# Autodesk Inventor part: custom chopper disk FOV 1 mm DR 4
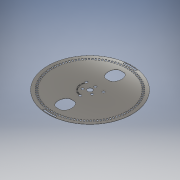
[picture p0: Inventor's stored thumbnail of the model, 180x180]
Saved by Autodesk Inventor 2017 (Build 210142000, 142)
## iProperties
Created: 2016-09
Part Number: custom chopper disk FOV 1 mm DR 4
Material: Generic
Document SubType Name: Modeling
Designer: Radek
Density: 1 g/cm^3
Appearance: Mirror
Author: Radek
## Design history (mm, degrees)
workplane "Work Plane1"
sketch "Sketch1"
  geometry: L1 (-46.781, 4.422)-(-44.253, 4.183) reference; L2 (-44.362, 2.791)-(-46.897, 2.951) reference; L3 (-46.411, 7.351)-(-43.903, 6.954) reference; L4 (-44.099, 5.571)-(-46.619, 5.889) reference; L5 (-45.858, 10.251)-(-43.38, 9.696) reference; L6 (-43.663, 8.329)-(-46.158, 8.805) reference; L7 (-45.124, 13.11)-(-42.685, 12.401) reference; L8 (-43.054, 11.054)-(-45.514, 11.686) reference; L9 (-44.212, 15.917)-(-41.822, 15.057) reference; L10 (-42.274, 13.736)-(-44.69, 14.521) reference; L11 (-43.125, 18.662)-(-40.794, 17.653) reference; L12 (-41.329, 16.363)-(-43.69, 17.298) reference; L13 (-41.868, 21.333)-(-39.605, 20.18) reference; L14 (-40.22, 18.926)-(-42.518, 20.007) reference; L15 (-40.446, 23.92)-(-38.26, 22.627) reference; L16 (-38.952, 21.414)-(-41.178, 22.638) reference; L17 (-38.865, 26.412)-(-36.764, 24.985) reference; L18 (-37.53, 23.818)-(-39.675, 25.179) reference; L19 (-37.129, 28.801)-(-35.122, 27.244) reference; L20 (-35.961, 26.127)-(-38.016, 27.62) reference; L21 (-35.248, 31.075)-(-33.342, 29.395) reference; L22 (-34.249, 28.333)-(-36.206, 29.953) reference; L23 (-33.227, 33.227)-(-31.431, 31.431) reference; L24 (-32.403, 30.428)-(-34.254, 32.167) reference; L25 (-31.075, 35.248)-(-29.395, 33.342) reference; L26 (-30.428, 32.403)-(-32.167, 34.254) reference; L27 (-28.801, 37.129)-(-27.244, 35.122) reference; L28 (-28.333, 34.249)-(-29.953, 36.206) reference; L29 (-26.412, 38.865)-(-24.985, 36.764) reference; L30 (-26.127, 35.961)-(-27.62, 38.016) reference; L31 (-23.92, 40.446)-(-22.627, 38.26) reference; L32 (-23.818, 37.53)-(-25.179, 39.675) reference; L33 (-21.333, 41.868)-(-20.18, 39.605) reference; L34 (-21.414, 38.952)-(-22.638, 41.178) reference; L35 (-18.662, 43.125)-(-17.653, 40.794) reference; L36 (-18.926, 40.22)-(-20.007, 42.518) reference; L37 (-15.917, 44.212)-(-15.057, 41.822) reference; L38 (-16.363, 41.329)-(-17.298, 43.69) reference; L39 (-13.11, 45.124)-(-12.401, 42.685) reference; L40 (-13.736, 42.274)-(-14.521, 44.69) reference; L41 (-10.251, 45.858)-(-9.696, 43.38) reference; L42 (-11.054, 43.054)-(-11.686, 45.514) reference; L43 (-7.351, 46.411)-(-6.954, 43.903) reference; L44 (-8.329, 43.663)-(-8.805, 46.158) reference; L45 (-4.422, 46.781)-(-4.183, 44.253) reference; L46 (-5.571, 44.099)-(-5.889, 46.619) reference; L47 (-1.476, 46.967)-(-1.396, 44.428) reference; L48 (-2.791, 44.362)-(-2.951, 46.897) reference; L49 (1.476, 46.967)-(1.396, 44.428) reference; L50 (0, 44.45)-(0, 46.99) reference; L51 (4.422, 46.781)-(4.183, 44.253) reference; L52 (2.791, 44.362)-(2.951, 46.897) reference; L53 (7.351, 46.411)-(6.954, 43.903) reference; L54 (5.571, 44.099)-(5.889, 46.619) reference; L55 (10.251, 45.858)-(9.696, 43.38) reference; L56 (8.329, 43.663)-(8.805, 46.158) reference; L57 (13.11, 45.124)-(12.401, 42.685) reference; L58 (11.054, 43.054)-(11.686, 45.514) reference; L59 (15.917, 44.212)-(15.057, 41.822) reference; L60 (13.736, 42.274)-(14.521, 44.69) reference; L61 (18.662, 43.125)-(17.653, 40.794) reference; L62 (16.363, 41.329)-(17.298, 43.69) reference; L63 (21.333, 41.868)-(20.18, 39.605) reference; L64 (18.926, 40.22)-(20.007, 42.518) reference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; C1 r 50.8 at (0, 0) reference; C2 r 2.984 at (0, 0) reference; C3 r 1.524 at (0, 6.553) reference; C4 r 1.524 at (10.339, 5.969) reference; C5 r 2.984 at (0, 0) reference; C6 r 1.524 at (0, -11.938) reference; C7 r 1.524 at (-5.675, -3.277) reference; C8 r 1.524 at (-10.339, 5.969) reference; C9 r 1.524 at (5.675, -3.277) reference; C10 r 50.8 at (0, 0) reference; C11 r 1.524 at (-5.675, -3.277) reference; C12 r 1.524 at (-10.339, 5.969) reference; C13 r 1.524 at (0, 6.553) reference; C14 r 1.524 at (10.339, 5.969) reference; C15 r 1.524 at (5.675, -3.277) reference; C16 r 1.524 at (0, -11.938) reference; C17 r 2.984 at (0, 0) reference; A1 r 17.081 centre (0, 0) between (0, -17.081) and (17.081, 0) reference; A2 r 17.081 centre (0, 0) between (0, 17.081) and (-17.081, 0) reference; A3 r 43.18 centre (0, 0) between (0, 43.18) and (-43.18, 0) reference; A4 r 43.18 centre (0, 0) between (0, -43.18) and (43.18, 0) reference; A5 r 44.45 centre (0, 0) between (-44.253, 4.183) and (-44.362, 2.791) reference; A6 r 46.99 centre (0, 0) between (-46.781, 4.422) and (-46.897, 2.951) reference; A7 r 44.45 centre (0, 0) between (-43.903, 6.954) and (-44.099, 5.571) reference; A8 r 46.99 centre (0, 0) between (-46.411, 7.351) and (-46.619, 5.889) reference; A9 r 44.45 centre (0, 0) between (-43.38, 9.696) and (-43.663, 8.329) reference; A10 r 46.99 centre (0, 0) between (-45.858, 10.251) and (-46.158, 8.805) reference; A11 r 44.45 centre (0, 0) between (-42.685, 12.401) and (-43.054, 11.054) reference; A12 r 46.99 centre (0, 0) between (-45.124, 13.11) and (-45.514, 11.686) reference; A13 r 44.45 centre (0, 0) between (-41.822, 15.057) and (-42.274, 13.736) reference; A14 r 46.99 centre (0, 0) between (-44.212, 15.917) and (-44.69, 14.521) reference; A15 r 44.45 centre (0, 0) between (-40.794, 17.653) and (-41.329, 16.363) reference; A16 r 46.99 centre (0, 0) between (-43.125, 18.662) and (-43.69, 17.298) reference; A17 r 44.45 centre (0, 0) between (-39.605, 20.18) and (-40.22, 18.926) reference; A18 r 46.99 centre (0, 0) between (-41.868, 21.333) and (-42.518, 20.007) reference; A19 r 44.45 centre (0, 0) between (-38.26, 22.627) and (-38.952, 21.414) reference; A20 r 46.99 centre (0, 0) between (-40.446, 23.92) and (-41.178, 22.638) reference; A21 r 44.45 centre (0, 0) between (-36.764, 24.985) and (-37.53, 23.818) reference; A22 r 46.99 centre (0, 0) between (-38.865, 26.412) and (-39.675, 25.179) reference; A23 r 44.45 centre (0, 0) between (-35.122, 27.244) and (-35.961, 26.127) reference; A24 r 46.99 centre (0, 0) between (-37.129, 28.801) and (-38.016, 27.62) reference; A25 r 44.45 centre (0, 0) between (-33.342, 29.395) and (-34.249, 28.333) reference; A26 r 46.99 centre (0, 0) between (-35.248, 31.075) and (-36.206, 29.953) reference; A27 r 44.45 centre (0, 0) between (-31.431, 31.431) and (-32.403, 30.428) reference; A28 r 46.99 centre (0, 0) between (-33.227, 33.227) and (-34.254, 32.167) reference; A29 r 44.45 centre (0, 0) between (-29.395, 33.342) and (-30.428, 32.403) reference; A30 r 46.99 centre (0, 0) between (-31.075, 35.248) and (-32.167, 34.254) reference; A31 r 44.45 centre (0, 0) between (-27.244, 35.122) and (-28.333, 34.249) reference; A32 r 46.99 centre (0, 0) between (-28.801, 37.129) and (-29.953, 36.206) reference; A33 r 44.45 centre (0, 0) between (-24.985, 36.764) and (-26.127, 35.961) reference; A34 r 46.99 centre (0, 0) between (-26.412, 38.865) and (-27.62, 38.016) reference; A35 r 44.45 centre (0, 0) between (-22.627, 38.26) and (-23.818, 37.53) reference; A36 r 46.99 centre (0, 0) between (-23.92, 40.446) and (-25.179, 39.675) reference; A37 r 44.45 centre (0, 0) between (-20.18, 39.605) and (-21.414, 38.952) reference; A38 r 46.99 centre (0, 0) between (-21.333, 41.868) and (-22.638, 41.178) reference; A39 r 44.45 centre (0, 0) between (-17.653, 40.794) and (-18.926, 40.22) reference; A40 r 46.99 centre (0, 0) between (-18.662, 43.125) and (-20.007, 42.518) reference; A41 r 44.45 centre (0, 0) between (-15.057, 41.822) and (-16.363, 41.329) reference; A42 r 46.99 centre (0, 0) between (-15.917, 44.212) and (-17.298, 43.69) reference; A43 r 44.45 centre (0, 0) between (-12.401, 42.685) and (-13.736, 42.274) reference; A44 r 46.99 centre (0, 0) between (-13.11, 45.124) and (-14.521, 44.69) reference; A45 r 44.45 centre (0, 0) between (-9.696, 43.38) and (-11.054, 43.054) reference; A46 r 46.99 centre (0, 0) between (-10.251, 45.858) and (-11.686, 45.514) reference; A47 r 44.45 centre (0, 0) between (-6.954, 43.903) and (-8.329, 43.663) reference; A48 r 46.99 centre (0, 0) between (-7.351, 46.411) and (-8.805, 46.158) reference; A49 r 44.45 centre (0, 0) between (-4.183, 44.253) and (-5.571, 44.099) reference; A50 r 46.99 centre (0, 0) between (-4.422, 46.781) and (-5.889, 46.619) reference; A51 r 44.45 centre (0, 0) between (-1.396, 44.428) and (-2.791, 44.362) reference; A52 r 46.99 centre (0, 0) between (-1.476, 46.967) and (-2.951, 46.897) reference; A53 r 44.45 centre (0, 0) between (1.396, 44.428) and (0, 44.45) reference; A54 r 46.99 centre (0, 0) between (1.476, 46.967) and (0, 46.99) reference; A55 r 44.45 centre (0, 0) between (4.183, 44.253) and (2.791, 44.362) reference; A56 r 46.99 centre (0, 0) between (4.422, 46.781) and (2.951, 46.897) reference; A57 r 44.45 centre (0, 0) between (6.954, 43.903) and (5.571, 44.099) reference; A58 r 46.99 centre (0, 0) between (7.351, 46.411) and (5.889, 46.619) reference; A59 r 44.45 centre (0, 0) between (9.696, 43.38) and (8.329, 43.663) reference; A60 r 46.99 centre (0, 0) between (10.251, 45.858) and (8.805, 46.158) reference; A61 r 44.45 centre (0, 0) between (12.401, 42.685) and (11.054, 43.054) reference; A62 r 46.99 centre (0, 0) between (13.11, 45.124) and (11.686, 45.514) reference; A63 r 44.45 centre (0, 0) between (15.057, 41.822) and (13.736, 42.274) reference; A64 r 46.99 centre (0, 0) between (15.917, 44.212) and (14.521, 44.69) reference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; 1 further point
  constraints: 8 end point, 2 collinear, 1 parallel
extrude "Extrusion2" new body sketch "Sketch1" distance "d2" = 0.254; taper "d3" = 0 deg
sketch "Sketch2"
  geometry: L1 (-46.781, 4.422)-(-44.253, 4.183) reference; L2 (-44.362, 2.791)-(-46.897, 2.951) reference; L3 (-46.411, 7.351)-(-43.903, 6.954) reference; L4 (-44.099, 5.571)-(-46.619, 5.889) reference; L5 (-45.858, 10.251)-(-43.38, 9.696) reference; L6 (-43.663, 8.329)-(-46.158, 8.805) reference; L7 (-45.124, 13.11)-(-42.685, 12.401) reference; L8 (-43.054, 11.054)-(-45.514, 11.686) reference; L9 (-44.212, 15.917)-(-41.822, 15.057) reference; L10 (-42.274, 13.736)-(-44.69, 14.521) reference; L11 (-43.125, 18.662)-(-40.794, 17.653) reference; L12 (-41.329, 16.363)-(-43.69, 17.298) reference; L13 (-41.868, 21.333)-(-39.605, 20.18) reference; L14 (-40.22, 18.926)-(-42.518, 20.007) reference; L15 (-40.446, 23.92)-(-38.26, 22.627) reference; L16 (-38.952, 21.414)-(-41.178, 22.638) reference; L17 (-38.865, 26.412)-(-36.764, 24.985) reference; L18 (-37.53, 23.818)-(-39.675, 25.179) reference; L19 (-37.129, 28.801)-(-35.122, 27.244) reference; L20 (-35.961, 26.127)-(-38.016, 27.62) reference; L21 (-35.248, 31.075)-(-33.342, 29.395) reference; L22 (-34.249, 28.333)-(-36.206, 29.953) reference; L23 (-33.227, 33.227)-(-31.431, 31.431) reference; L24 (-32.403, 30.428)-(-34.254, 32.167) reference; L25 (-31.075, 35.248)-(-29.395, 33.342) reference; L26 (-30.428, 32.403)-(-32.167, 34.254) reference; L27 (-28.801, 37.129)-(-27.244, 35.122) reference; L28 (-28.333, 34.249)-(-29.953, 36.206) reference; L29 (-26.412, 38.865)-(-24.985, 36.764) reference; L30 (-26.127, 35.961)-(-27.62, 38.016) reference; L31 (-23.92, 40.446)-(-22.627, 38.26) reference; L32 (-23.818, 37.53)-(-25.179, 39.675) reference; L33 (-21.333, 41.868)-(-20.18, 39.605) reference; L34 (-21.414, 38.952)-(-22.638, 41.178) reference; L35 (-18.662, 43.125)-(-17.653, 40.794) reference; L36 (-18.926, 40.22)-(-20.007, 42.518) reference; L37 (-15.917, 44.212)-(-15.057, 41.822) reference; L38 (-16.363, 41.329)-(-17.298, 43.69) reference; L39 (-13.11, 45.124)-(-12.401, 42.685) reference; L40 (-13.736, 42.274)-(-14.521, 44.69) reference; L41 (-10.251, 45.858)-(-9.696, 43.38) reference; L42 (-11.054, 43.054)-(-11.686, 45.514) reference; L43 (-7.351, 46.411)-(-6.954, 43.903) reference; L44 (-8.329, 43.663)-(-8.805, 46.158) reference; L45 (-4.422, 46.781)-(-4.183, 44.253) reference; L46 (-5.571, 44.099)-(-5.889, 46.619) reference; L47 (-1.476, 46.967)-(-1.396, 44.428) reference; L48 (-2.791, 44.362)-(-2.951, 46.897) reference; L49 (1.476, 46.967)-(1.396, 44.428) reference; L50 (0, 44.45)-(0, 46.99) reference; L51 (4.422, 46.781)-(4.183, 44.253) reference; L52 (2.791, 44.362)-(2.951, 46.897) reference; L53 (7.351, 46.411)-(6.954, 43.903) reference; L54 (5.571, 44.099)-(5.889, 46.619) reference; L55 (10.251, 45.858)-(9.696, 43.38) reference; L56 (8.329, 43.663)-(8.805, 46.158) reference; L57 (13.11, 45.124)-(12.401, 42.685) reference; L58 (11.054, 43.054)-(11.686, 45.514) reference; L59 (15.917, 44.212)-(15.057, 41.822) reference; L60 (13.736, 42.274)-(14.521, 44.69) reference; L61 (18.662, 43.125)-(17.653, 40.794) reference; L62 (16.363, 41.329)-(17.298, 43.69) reference; L63 (21.333, 41.868)-(20.18, 39.605) reference; L64 (18.926, 40.22)-(20.007, 42.518) reference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; C1 r 50.8 at (0, 0) reference; C2 r 1.524 at (-5.675, -3.277) reference; C3 r 1.524 at (-10.339, 5.969) reference; C4 r 1.524 at (0, 6.553) reference; C5 r 1.524 at (10.339, 5.969) reference; C6 r 1.524 at (5.675, -3.277) reference; C7 r 1.524 at (0, -11.938) reference; C8 r 2.984 at (0, 0) reference; A1 r 44.45 centre (0, 0) between (-44.253, 4.183) and (-44.362, 2.791) reference; A2 r 46.99 centre (0, 0) between (-46.781, 4.422) and (-46.897, 2.951) reference; A3 r 44.45 centre (0, 0) between (-43.903, 6.954) and (-44.099, 5.571) reference; A4 r 46.99 centre (0, 0) between (-46.411, 7.351) and (-46.619, 5.889) reference; A5 r 44.45 centre (0, 0) between (-43.38, 9.696) and (-43.663, 8.329) reference; A6 r 46.99 centre (0, 0) between (-45.858, 10.251) and (-46.158, 8.805) reference; A7 r 44.45 centre (0, 0) between (-42.685, 12.401) and (-43.054, 11.054) reference; A8 r 46.99 centre (0, 0) between (-45.124, 13.11) and (-45.514, 11.686) reference; A9 r 44.45 centre (0, 0) between (-41.822, 15.057) and (-42.274, 13.736) reference; A10 r 46.99 centre (0, 0) between (-44.212, 15.917) and (-44.69, 14.521) reference; A11 r 44.45 centre (0, 0) between (-40.794, 17.653) and (-41.329, 16.363) reference; A12 r 46.99 centre (0, 0) between (-43.125, 18.662) and (-43.69, 17.298) reference; A13 r 44.45 centre (0, 0) between (-39.605, 20.18) and (-40.22, 18.926) reference; A14 r 46.99 centre (0, 0) between (-41.868, 21.333) and (-42.518, 20.007) reference; A15 r 44.45 centre (0, 0) between (-38.26, 22.627) and (-38.952, 21.414) reference; A16 r 46.99 centre (0, 0) between (-40.446, 23.92) and (-41.178, 22.638) reference; A17 r 44.45 centre (0, 0) between (-36.764, 24.985) and (-37.53, 23.818) reference; A18 r 46.99 centre (0, 0) between (-38.865, 26.412) and (-39.675, 25.179) reference; A19 r 44.45 centre (0, 0) between (-35.122, 27.244) and (-35.961, 26.127) reference; A20 r 46.99 centre (0, 0) between (-37.129, 28.801) and (-38.016, 27.62) reference; A21 r 44.45 centre (0, 0) between (-33.342, 29.395) and (-34.249, 28.333) reference; A22 r 46.99 centre (0, 0) between (-35.248, 31.075) and (-36.206, 29.953) reference; A23 r 44.45 centre (0, 0) between (-31.431, 31.431) and (-32.403, 30.428) reference; A24 r 46.99 centre (0, 0) between (-33.227, 33.227) and (-34.254, 32.167) reference; A25 r 44.45 centre (0, 0) between (-29.395, 33.342) and (-30.428, 32.403) reference; A26 r 46.99 centre (0, 0) between (-31.075, 35.248) and (-32.167, 34.254) reference; A27 r 44.45 centre (0, 0) between (-27.244, 35.122) and (-28.333, 34.249) reference; A28 r 46.99 centre (0, 0) between (-28.801, 37.129) and (-29.953, 36.206) reference; A29 r 44.45 centre (0, 0) between (-24.985, 36.764) and (-26.127, 35.961) reference; A30 r 46.99 centre (0, 0) between (-26.412, 38.865) and (-27.62, 38.016) reference; A31 r 44.45 centre (0, 0) between (-22.627, 38.26) and (-23.818, 37.53) reference; A32 r 46.99 centre (0, 0) between (-23.92, 40.446) and (-25.179, 39.675) reference; A33 r 44.45 centre (0, 0) between (-20.18, 39.605) and (-21.414, 38.952) reference; A34 r 46.99 centre (0, 0) between (-21.333, 41.868) and (-22.638, 41.178) reference; A35 r 44.45 centre (0, 0) between (-17.653, 40.794) and (-18.926, 40.22) reference; A36 r 46.99 centre (0, 0) between (-18.662, 43.125) and (-20.007, 42.518) reference; A37 r 44.45 centre (0, 0) between (-15.057, 41.822) and (-16.363, 41.329) reference; A38 r 46.99 centre (0, 0) between (-15.917, 44.212) and (-17.298, 43.69) reference; A39 r 44.45 centre (0, 0) between (-12.401, 42.685) and (-13.736, 42.274) reference; A40 r 46.99 centre (0, 0) between (-13.11, 45.124) and (-14.521, 44.69) reference; A41 r 44.45 centre (0, 0) between (-9.696, 43.38) and (-11.054, 43.054) reference; A42 r 46.99 centre (0, 0) between (-10.251, 45.858) and (-11.686, 45.514) reference; A43 r 44.45 centre (0, 0) between (-6.954, 43.903) and (-8.329, 43.663) reference; A44 r 46.99 centre (0, 0) between (-7.351, 46.411) and (-8.805, 46.158) reference; A45 r 44.45 centre (0, 0) between (-4.183, 44.253) and (-5.571, 44.099) reference; A46 r 46.99 centre (0, 0) between (-4.422, 46.781) and (-5.889, 46.619) reference; A47 r 44.45 centre (0, 0) between (-1.396, 44.428) and (-2.791, 44.362) reference; A48 r 46.99 centre (0, 0) between (-1.476, 46.967) and (-2.951, 46.897) reference; A49 r 44.45 centre (0, 0) between (1.396, 44.428) and (0, 44.45) reference; A50 r 46.99 centre (0, 0) between (1.476, 46.967) and (0, 46.99) reference; A51 r 44.45 centre (0, 0) between (4.183, 44.253) and (2.791, 44.362) reference; A52 r 46.99 centre (0, 0) between (4.422, 46.781) and (2.951, 46.897) reference; A53 r 44.45 centre (0, 0) between (6.954, 43.903) and (5.571, 44.099) reference; A54 r 46.99 centre (0, 0) between (7.351, 46.411) and (5.889, 46.619) reference; A55 r 44.45 centre (0, 0) between (9.696, 43.38) and (8.329, 43.663) reference; A56 r 46.99 centre (0, 0) between (10.251, 45.858) and (8.805, 46.158) reference; A57 r 44.45 centre (0, 0) between (12.401, 42.685) and (11.054, 43.054) reference; A58 r 46.99 centre (0, 0) between (13.11, 45.124) and (11.686, 45.514) reference; A59 r 44.45 centre (0, 0) between (15.057, 41.822) and (13.736, 42.274) reference; A60 r 46.99 centre (0, 0) between (15.917, 44.212) and (14.521, 44.69) reference; A61 r 44.45 centre (0, 0) between (17.653, 40.794) and (16.363, 41.329) reference; A62 r 46.99 centre (0, 0) between (18.662, 43.125) and (17.298, 43.69) reference; A63 r 44.45 centre (0, 0) between (20.18, 39.605) and (18.926, 40.22) reference; A64 r 46.99 centre (0, 0) between (21.333, 41.868) and (20.007, 42.518) reference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; 1 further point
  constraints: 8 end point, 1 collinear
extrude "Extrusion3" cut sketch "Sketch2" stored distance "d4" = 0.254; taper "d5" = 0 deg
sketch "Sketch3" dims "d20" = 6.21111 (= 0.5 x holediameter), "d21" = 8.78384 (= 1.41421 x d20)
  geometry: L1 (-10.339, 5.969)-(10.339, 5.969); L2 (0, 0)-(50.8, 0); L3 (0, 44.45)-(0, 46.99) reference; L4 (0, 0)-(0, 50.8); L5 (0, 30)-(0, 21.216); L6 (0, 50.165)-(0, 48.26) reference; L7 (-48.26, 0)-(-50.165, 0) reference; L8 (0, 0)-(9.809, 34.946); L9 (0, 50.8)-(0, 50.165); L10 (1.281, 21.177)-(2.555, 38.695); L11 (-1.281, 21.177)-(-2.555, 38.695); C1 r 2.984 at (0, 0) reference; C2 r 15.25 at (0, 0); C3 r 1.524 at (-10.339, 5.969) reference; C4 r 1.524 at (0, -11.938) reference; C5 r 1.524 at (10.339, 5.969) reference; C6 r 1.524 at (-5.675, -3.277) reference; C7 r 1.524 at (5.675, -3.277) reference; A1 r 50.8 centre (0, 0) between (50.8, 0) and (0, 50.8) reference; A2 r 48.26 centre (0, 0) between (0, 48.26) and (-48.26, 0) reference; A3 r 50.165 centre (0, 0) between (0, 50.165) and (-50.165, 0) reference; A4 r 50.165 centre (0, 0) between (-20.154, -45.939) and (22.037, -45.066); A5 r 48.26 centre (0, 0) between (-19.033, -44.348) and (20.956, -43.472); 3 further points; 3 other entities
  constraints: 16 end point, 8 point on circle, 3 centre point, 3 coincident, 2 vertical, 1 collinear, 1 horizontal, 1 parallel, 1 point on line, 1 vertical alignment, 19 other
  dimensions: "d9" = 30.5 diameter of C2; "d18" = 0 distance between parallel lines of L4 L5; "d19" = 30 distance of point (0, 0) L5.start (= offaxis); "d24" = 0.60415 dimension on point (0, 0) L5.start point (-1.811, 29.945) (= 0.5 x angle); "d28" = 0.60415 dimension on point (0, 0) point (1.811, 29.945) L5.start (= 0.5 x angle); "d32" = 0.635 distance of L4.end L6.start (derived)
extrude "Extrusion7" cut sketch "Sketch3" stored distance "d40" = 10; taper "d41" = 0 deg
sketch "Sketch4"
  geometry: L1 (-2.555, 38.695)-(-1.281, 21.177) reference; L2 (1.281, 21.177)-(2.555, 38.695) reference; L3 (2.555, 38.695)-(1.281, 21.177) reference; L4 (-1.281, 21.177)-(-2.555, 38.695) reference; L5 (-1.281, 21.177)-(-2.555, 38.695); L6 (1.281, 21.177)-(2.555, 38.695); C1 r 2.984 at (0, 0) reference; C2 r 50.8 at (0, 0) reference; A1 r 21.216 centre (0, 0) between (1.281, 21.177) and (-1.281, 21.177); A2 r 38.779 centre (0, 0) between (2.555, 38.695) and (-2.555, 38.695); 3 further points; 2 other entities
  constraints: 4 end point, 4 point on circle, 2 centre point, 2 coincident, 2 collinear, 2 other
extrude "Extrusion8" cut sketch "Sketch4" stored distance "d42" = 10; taper "d43" = 0 deg
sketch "Sketch5"
  geometry: L1 (0, 0)-(-7.947, 50.175); L2 (0, 0)-(7.947, 50.175); L3 (7.524, 47.508)-(7.837, 49.483); L4 (-7.524, 47.508)-(-7.837, 49.483); L5 (6.954, 43.903)-(7.351, 46.411) reference; L6 (4.422, 46.781)-(4.183, 44.253) reference; L7 (7.351, 46.411)-(6.954, 43.903) reference; C1 r 2.984 at (0, 0) reference; A1 r 50.8 centre (0, 0) between (-7.947, 50.175) and (7.947, 50.175) reference; A2 r 21.216 centre (0, 0) between (1.281, 21.177) and (-1.281, 21.177) reference; A3 r 38.779 centre (0, 0) between (2.555, 38.695) and (-2.555, 38.695) reference; A4 r 48.1 centre (0, 0) between (7.524, 47.508) and (-7.524, 47.508); A5 r 50.1 centre (0, 0) between (7.837, 49.483) and (-7.837, 49.483); 4 further points; 2 other entities
  constraints: 8 end point, 6 point on circle, 3 point on line, 2 centre point, 2 coincident, 2 collinear, 1 midpoint, 8 other
  dimensions: "d44" = 0.7 radial gap between concentric circles of A1 A5; "d45" = 2 radial gap between concentric circles of A5 A4; "d53" = 18 deg angle of L1 L2
extrude "Extrusion9" cut sketch "Sketch5" stored distance "d46" = 10; taper "d47" = 0 deg
pattern_circular "Circular Pattern3" dims angle "d49" = 360 deg
sketch "Sketch6"
  geometry: L1 (21.216, 0)-(21.177, 0) reference; L2 (38.695, 0)-(38.779, 0) reference; L3 (21.177, -0.254)-(21.216, -0.254) reference; L4 (38.779, -0.254)-(38.695, -0.254) reference; L5 (-50.8, 0)-(50.8, 0) reference; L6 (-50.8, -0.254)-(50.8, -0.254) reference; L7 (21.216, 0)-(38.779, 0); L8 (21.216, -0.254)-(38.779, -0.254); L9 (29.998, -0.254)-(29.998, 0); L10 (29.998, -0.127)-(32.933, -3.062); 1 further point
  constraints: 8 end point, 3 midpoint, 1 collinear, 1 parallel
  dimensions: "d51" = 135 deg angle of L10 L9
workaxis "Work Axis1"
workplane "Work Plane3"
  workplane "Work Plane2"
sketch "Sketch7"
  geometry: L1 (0, -11.938)-(-10.339, 5.969); C1 r 1.524 at (0, -11.938) reference; C2 r 1.524 at (-10.339, 5.969) reference; C3 r 2.984 at (0, 0) reference; C4 r 10.414 at (0, 0); 2 further points
  constraints: 2 end point, 1 centre point, 1 coincident, 1 tangent, 1 other
extrude "Extrusion11" cut sketch "Sketch7" stored distance "d57" = 10; taper "d58" = 0 deg
body "Solid2"
pattern_circular "Circular Pattern1" dims angle "d7" = 360 deg
node "Reference1"
node "Reference2"
node "Reference3"
node "Reference4"
node "Reference5"
node "Reference6"
node "Reference7"
node "Reference8"
node "Reference9"
node "Reference10"
node "Reference11"
node "Reference12"
node "Reference13"
node "Reference14"
node "Reference15"
node "Reference16"
node "Reference17"
node "Reference18"
node "Reference19"
other parameters: "d12" = 6.61111 (computed from ftube, FOV), "FOV" = 1 [user parameter; used in 2 equation terms], "dutycycle" = 1.70265 (computed from holelength, offaxis) [user parameter], "offaxis" = 30 [user parameter; used in 4 equation terms], "angle" = 1.2083 (computed from holediameter, holelength, offaxis) [user parameter; used in 2 equation terms], "holelength" = 16.04714 (computed from dutyratio, offaxis, holediameter) [user parameter; used in 2 equation terms], "holediameter" = 12.42222 (computed from FOV, ftube) [user parameter; used in 3 equation terms], "dutyratio" = 0.4 [user parameter; used in 1 equation term], "d52" = 45 deg
